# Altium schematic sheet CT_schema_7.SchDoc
size 255 x 245 mm
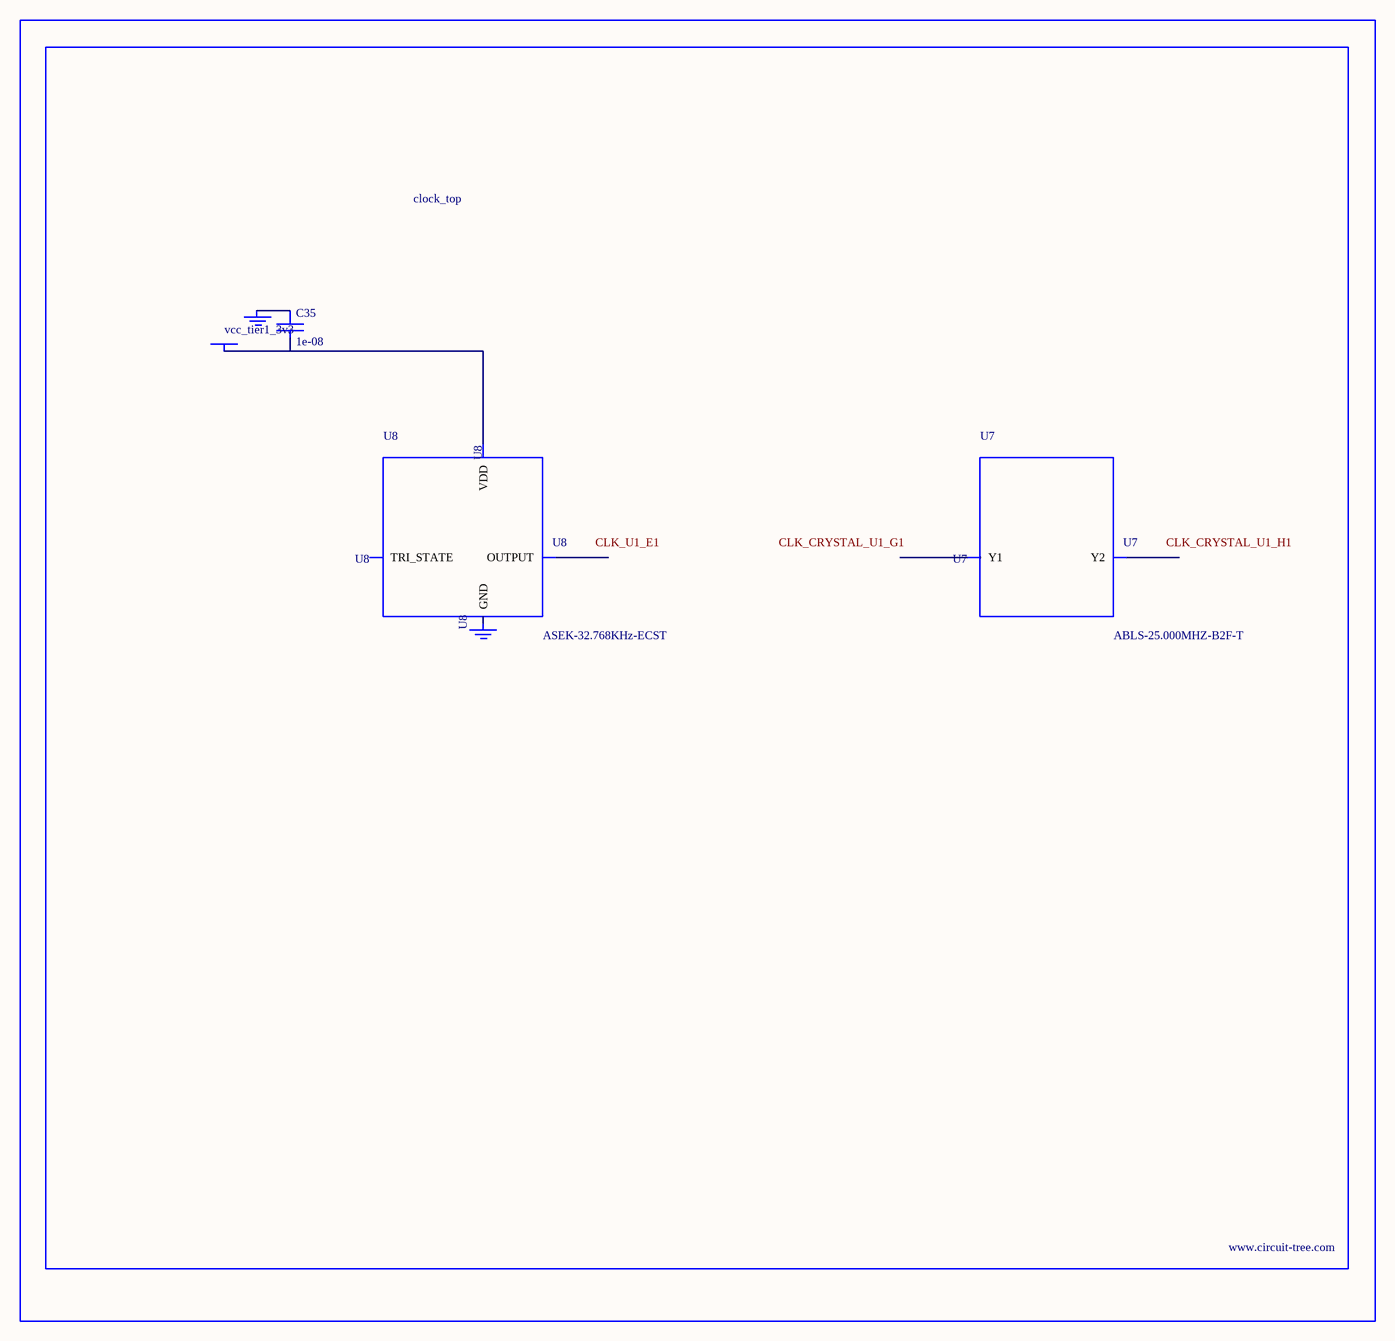
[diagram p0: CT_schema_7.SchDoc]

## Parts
BORDER6  (no value)
C35  1e-08  [C0402]
GND_INSTANCE_6_0  (no value)
GND_INSTANCE_6_1  (no value)
POWER_INSTANCE_6_0  vcc_tier1_3v3
U7  ABLS-25.000MHZ-B2F-T  [ABLS-25.000MHZ-B2F-T]
U8  ASEK-32.768KHz-ECST  [ASEK]

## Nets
NetC35_1: C35.1 GND_INSTANCE_6_0.0(GND)
NetC35_2: C35.2 POWER_INSTANCE_6_0.0(PWR) U8.4(VDD)

Not connected (* = marked no-connect by the designer): GND_INSTANCE_6_1 0(GND); U7 1(Y1) 2(Y2); U8 1(TRI_STATE) 2(GND) 3(OUTPUT)

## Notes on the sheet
- Labels drawn without touching a wire or pin: CLK_CRYSTAL_U1_G1, CLK_CRYSTAL_U1_H1, CLK_U1_E1

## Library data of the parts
BORDER6 = BORDER_PAGE6
C35 = C0402C103K3RAC
GND_INSTANCE_6_0 GND_INSTANCE_6_1 = GND
POWER_INSTANCE_6_0 = PWR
